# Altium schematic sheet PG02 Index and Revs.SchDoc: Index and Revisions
size B; Date: 2/10/2009; ApprovedBy: Touraj; DrawnBy: Juan A. Nadal; Engineer: Touraj; Organization: ActiveWave; Address1: 902 Clint Moore Rd., Suite 118; Address2: Boca Raton; Address3: FL, 33487; Address4: 561-999-9422; DocumentNumber: 2; Revision: 18; SheetNumber: 2; SheetTotal: 4; PageSetup: Record=PageOptions|CenterHorizontal=True|CenterVertical=True|PrintScale=0.68|XCorrection=1.00|YCorrection=1.00|PrintKind=0|BorderSize=5000000|LeftOffset=0|BottomOffset=0|Orientation=2|PaperLength=1000|PaperWidth=1000|Scale=100|PaperSource=7|PrintQuality=-4|MediaType=1|DitherType=10|PaperKind=Letter|PrintScaleMode=1; Project: Tag105
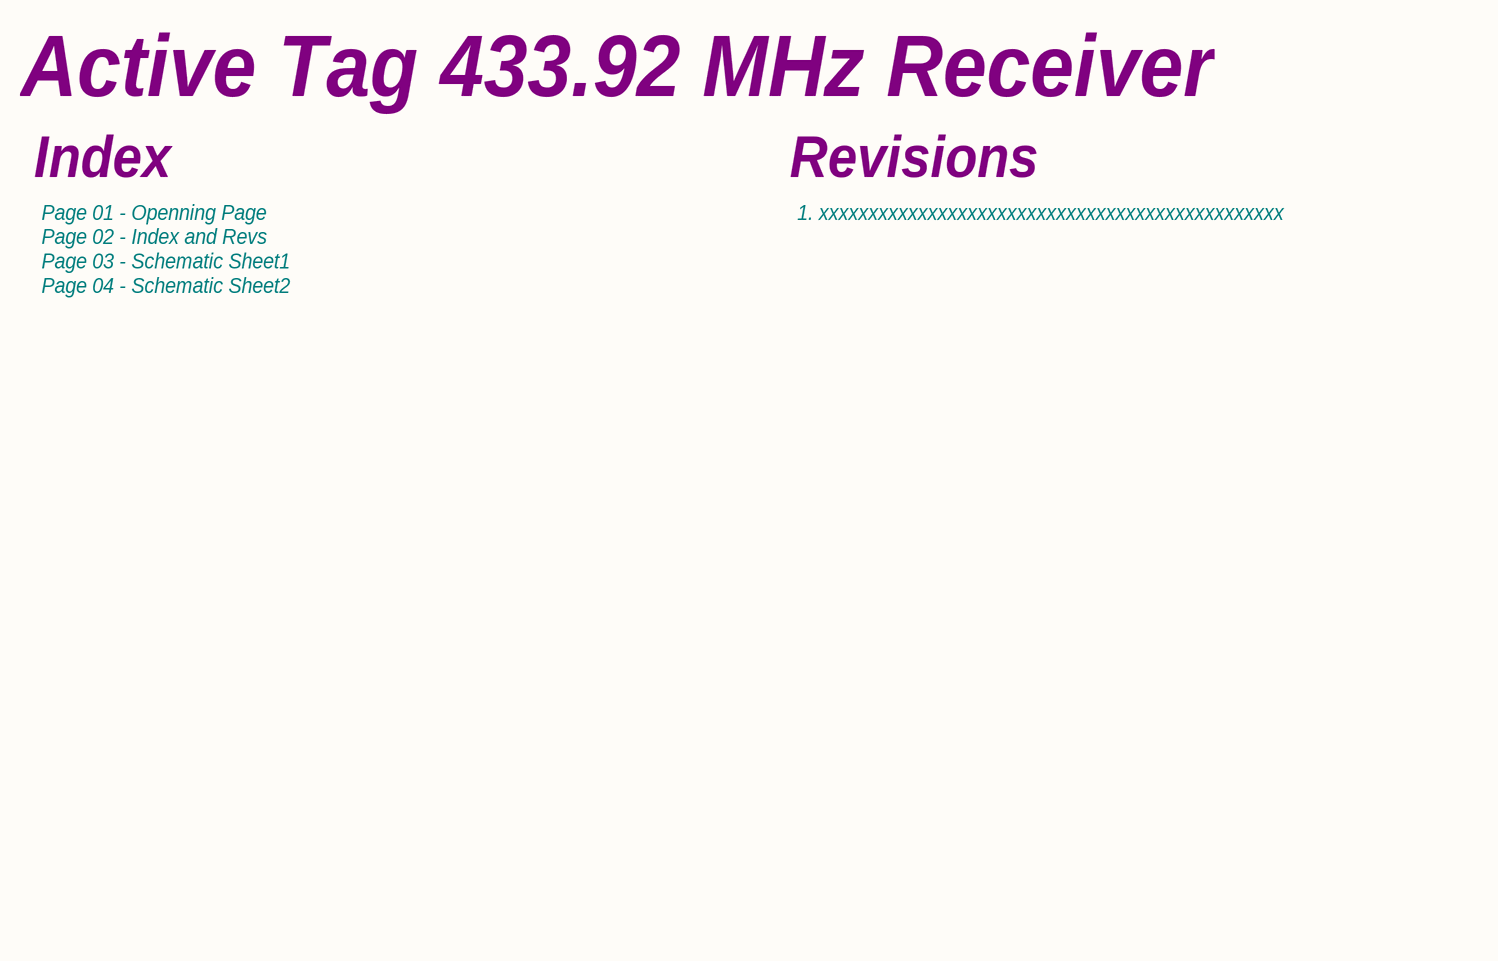
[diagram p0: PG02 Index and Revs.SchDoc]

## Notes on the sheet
- Active Tag 433.92 MHz Receiver
- Index
- Revisions
- Page 01 - Openning Page
  Page 02 - Index and Revs
  Page 03 - Schematic Sheet1
  Page 04 - Schematic Sheet2
- 1. xxxxxxxxxxxxxxxxxxxxxxxxxxxxxxxxxxxxxxxxxxxxxxx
